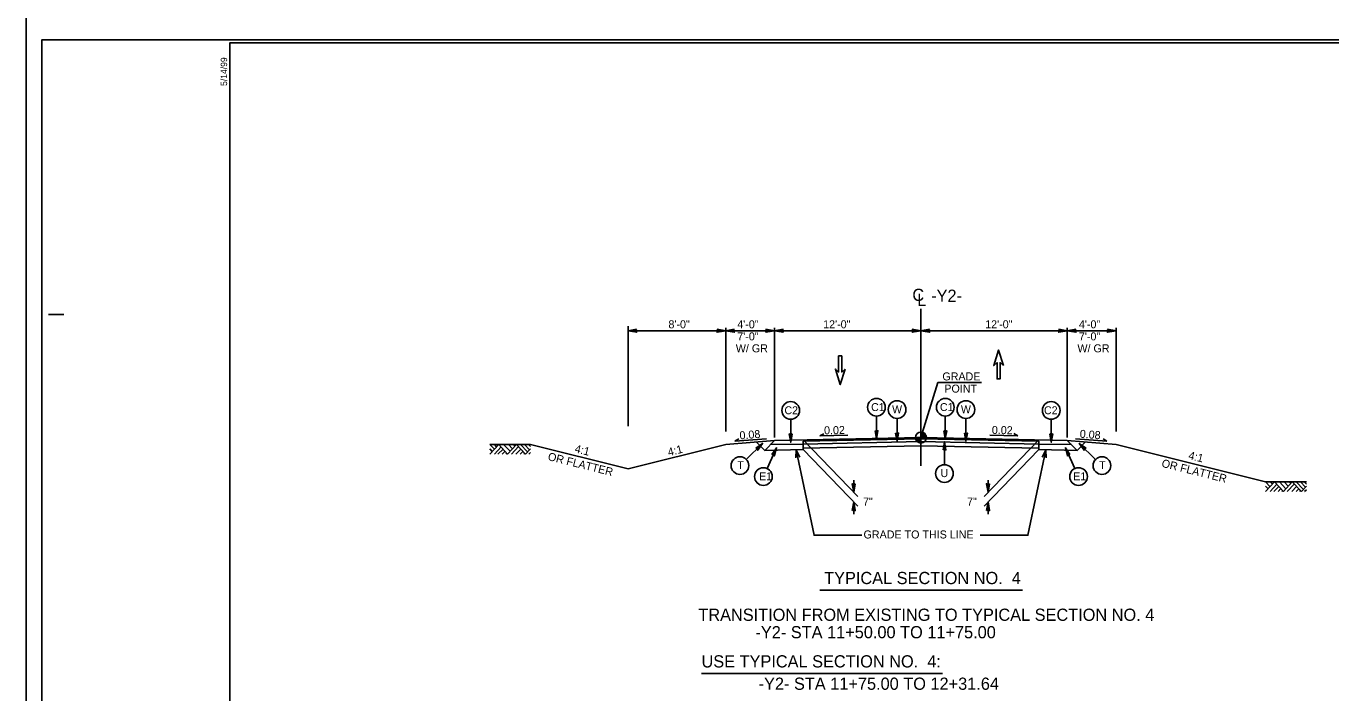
# Model space of a CAD drawing. Extents: x 1901718 to 1902220, y 193828 to 194187.
# Drawn here: x 1901965.8 to 1902072.8, y 193882.3 to 193936.9 of the extents above; entities that cross this region are included whole.
import ezdxf

# ---------------------------------------------------------------- set-up
doc = ezdxf.new("R2010")
doc.units = 0
for name, color, linetype in [('Old_Level_1', 7, 'Continuous'), ('Old_Level_11', 7, 'Continuous'), ('Old_Level_2', 7, 'Continuous'), ('Old_Level_20', 7, 'Continuous'), ('Old_Level_3', 7, 'Continuous'), ('Prop Dimension', 7, 'Continuous'), ('Sheet Border Standard 30in CELL', 7, 'Continuous'), ('Sheet Cutting Line CELL', 7, 'Continuous'), ('Sheet Plot Border Inside CELL', 7, 'Continuous'), ('Sheet Plot Border Outside CELL', 7, 'Continuous'), ('Typical Terminator CELL', 7, 'Continuous')]:
    doc.layers.add(name, color=color, linetype=linetype)

# ---------------------------------------------------------------- blocks, each defined once
blk = doc.blocks.new('TERMINATOR')
at = {"layer": 'Typical Terminator CELL'}
blk.add_lwpolyline([(-0.469, 0.081), (0, 0), (-0.471, -0.083), (-0.411, 0)], close=True, dxfattribs=at)

msp = doc.modelspace()

# ---------------------------------------------------------------- linework, layer by layer
at = {"layer": 'Old_Level_1'}
for p, q in [((1902039.18, 193900.87), (1902039.18, 193913.73)), ((1902023.18, 193903.68), (1902023.18, 193912.18)), ((1902027.18, 193903.18), (1902027.18, 193912.18)), ((1902051.18, 193903.18), (1902051.18, 193912.18)), ((1902055.18, 193903.68), (1902055.18, 193912.18)), ((1902015.18, 193911.93), (1902023.18, 193911.93)), ((1902023.18, 193911.93), (1902027.18, 193911.93)), ((1902027.18, 193911.93), (1902039.18, 193911.93)), ((1902051.18, 193911.93), (1902039.18, 193911.93)), ((1902055.18, 193911.93), (1902051.18, 193911.93)), ((1902039.18, 193903.18), (1902039.18, 193903.63)), ((1902047.12, 193903.32), (1902046.8, 193903.51)), ((1902003.84, 193902.62), (1902004.22, 193902.22)), ((1902003.84, 193901.81), (1902004.58, 193902.61)), ((1902004.22, 193902.62), (1902004.4, 193902.42)), ((1902004.58, 193902.61), (1902005.31, 193901.83)), ((1902004.97, 193902.62), (1902005.51, 193902.05)), ((1902005.31, 193901.83), (1902006.04, 193902.62)), ((1902005.37, 193902.62), (1902005.71, 193902.26)), ((1902005.62, 193901.81), (1902006.2, 193902.44)), ((1902005.77, 193902.62), (1902005.91, 193902.48)), ((1902006.04, 193902.62), (1902006.78, 193901.82)), ((1902006.36, 193902.62), (1902006.94, 193902)), ((1902006.69, 193902.62), (1902007.11, 193902.17)), ((1902007.01, 193902.62), (1902007.18, 193902.44)), ((1902007.18, 193902.62), (1902015.18, 193900.62)), ((1902023.18, 193902.62), (1902015.18, 193900.62)), ((1902027.18, 193902.94), (1902023.18, 193902.62)), ((1902026.52, 193903.08), (1902023.94, 193902.87)), ((1902023.94, 193902.87), (1902024.26, 193903.06)), ((1902026.38, 193902.13), (1902025.69, 193902.82)), ((1902027.18, 193902.94), (1902026.38, 193902.13)), ((1902029.53, 193902.65), (1902026.84, 193902.6)), ((1902039.18, 193903.18), (1902027.18, 193902.94)), ((1902039.18, 193903.07), (1902029.53, 193902.88)), ((1902029.53, 193902.99), (1902034, 193898.36)), ((1902029.53, 193902.88), (1902029.53, 193902.19)), ((1902039.18, 193902.85), (1902029.53, 193902.65)), ((1902039.18, 193902.51), (1902029.54, 193902.32)), ((1902030.9, 193903.32), (1902031.23, 193903.49)), ((1902033.2, 193903.37), (1902030.9, 193903.32)), ((1902038.73, 193903.18), (1902039.18, 193903.18)), ((1902039.63, 193903.18), (1902039.18, 193903.18)), ((1902039.18, 193902.73), (1902039.18, 193903.18)), ((1902039.18, 193903.18), (1902039.18, 193902.73)), ((1902039.18, 193903.18), (1902051.18, 193902.94)), ((1902039.18, 193903.07), (1902048.84, 193902.88)), ((1902039.18, 193902.85), (1902048.84, 193902.65)), ((1902039.18, 193902.51), (1902048.83, 193902.32)), ((1902048.84, 193902.99), (1902044.36, 193898.36)), ((1902044.82, 193903.37), (1902047.12, 193903.32)), ((1902048.84, 193902.88), (1902048.84, 193902.19)), ((1902048.84, 193902.65), (1902051.52, 193902.6)), ((1902051.18, 193902.94), (1902051.99, 193902.13)), ((1902051.18, 193902.94), (1902055.18, 193902.62)), ((1902051.85, 193903.08), (1902054.43, 193902.87)), ((1902051.99, 193902.13), (1902052.68, 193902.82)), ((1902054.43, 193902.87), (1902054.11, 193903.06)), ((1902055.18, 193902.62), (1902067.43, 193899.56)), ((1902003.84, 193902.26), (1902004.05, 193902.03)), ((1902004.22, 193901.81), (1902004.77, 193902.41)), ((1902004.52, 193901.81), (1902004.93, 193902.24)), ((1902004.87, 193901.81), (1902005.1, 193902.06)), ((1902005.18, 193901.81), (1902005.25, 193901.89)), ((1902005.99, 193901.81), (1902006.39, 193902.24)), ((1902006.35, 193901.81), (1902006.57, 193902.05)), ((1902006.65, 193901.81), (1902006.72, 193901.89)), ((1902006.78, 193901.82), (1902007.18, 193902.26)), ((1902007.05, 193901.81), (1902007.18, 193901.96)), ((1902029.53, 193902.19), (1902026.38, 193902.13)), ((1902029.53, 193902.19), (1902034, 193897.57)), ((1902048.84, 193902.19), (1902044.36, 193897.57)), ((1902048.84, 193902.19), (1902051.99, 193902.13)), ((1902033.68, 193899.69), (1902033.68, 193898.69)), ((1902044.68, 193899.69), (1902044.68, 193898.69)), ((1902033.68, 193897.9), (1902033.68, 193896.9)), ((1902044.68, 193897.9), (1902044.68, 193896.9))]:
    msp.add_line(p, q, dxfattribs=at)
for points in [[(1902039.19, 193903.63), (1902039.19, 193903.63), (1902039.19, 193903.18)], [(1902039.2, 193903.63), (1902039.2, 193903.18)], [(1902039.21, 193903.63), (1902039.21, 193903.18)], [(1902039.21, 193903.63), (1902039.21, 193903.18)], [(1902039.22, 193903.63), (1902039.22, 193903.18)], [(1902039.23, 193903.63), (1902039.23, 193903.18)], [(1902039.24, 193903.62), (1902039.24, 193903.18)], [(1902039.25, 193903.62), (1902039.25, 193903.18)], [(1902039.26, 193903.62), (1902039.26, 193903.18)], [(1902039.27, 193903.62), (1902039.27, 193903.18)], [(1902039.28, 193903.62), (1902039.28, 193903.18)], [(1902039.29, 193903.62), (1902039.29, 193903.18)], [(1902039.3, 193903.61), (1902039.3, 193903.18)], [(1902039.3, 193903.61), (1902039.3, 193903.18)], [(1902039.31, 193903.61), (1902039.31, 193903.18)], [(1902039.32, 193903.61), (1902039.32, 193903.18)], [(1902039.33, 193903.6), (1902039.33, 193903.18)], [(1902039.34, 193903.6), (1902039.34, 193903.18)], [(1902039.35, 193903.6), (1902039.35, 193903.18)], [(1902039.36, 193903.59), (1902039.36, 193903.18)], [(1902039.37, 193903.59), (1902039.37, 193903.18)], [(1902039.38, 193903.58), (1902039.38, 193903.18)], [(1902039.39, 193903.58), (1902039.39, 193903.18)], [(1902039.39, 193903.58), (1902039.39, 193903.18)], [(1902039.4, 193903.57), (1902039.4, 193903.18)], [(1902039.41, 193903.57), (1902039.41, 193903.18)], [(1902039.42, 193903.56), (1902039.42, 193903.18)], [(1902039.43, 193903.55), (1902039.43, 193903.18)], [(1902039.44, 193903.55), (1902039.44, 193903.18)], [(1902039.45, 193903.54), (1902039.45, 193903.18)], [(1902039.46, 193903.54), (1902039.46, 193903.18)], [(1902039.47, 193903.53), (1902039.47, 193903.18)], [(1902039.48, 193903.52), (1902039.48, 193903.18)], [(1902039.48, 193903.51), (1902039.48, 193903.18)], [(1902039.49, 193903.5), (1902039.49, 193903.18)], [(1902039.5, 193903.5), (1902039.5, 193903.18)], [(1902003.84, 193902.62), (1902007.18, 193902.62)], [(1902038.74, 193903.18), (1902038.74, 193903.13)], [(1902038.74, 193903.18), (1902038.74, 193903.08)], [(1902038.75, 193903.18), (1902038.75, 193903.04)], [(1902038.76, 193903.18), (1902038.76, 193903.02)], [(1902038.77, 193903.18), (1902038.77, 193903)], [(1902038.78, 193903.18), (1902038.78, 193902.98)], [(1902038.79, 193903.18), (1902038.79, 193902.96)], [(1902038.8, 193903.18), (1902038.8, 193902.94)], [(1902038.81, 193903.18), (1902038.81, 193902.93)], [(1902038.82, 193903.18), (1902038.82, 193902.92)], [(1902038.83, 193903.18), (1902038.83, 193902.91)], [(1902038.83, 193903.18), (1902038.83, 193902.89)], [(1902038.84, 193903.18), (1902038.84, 193902.88)], [(1902038.85, 193903.18), (1902038.85, 193902.87)], [(1902038.86, 193903.18), (1902038.86, 193902.86)], [(1902038.87, 193903.18), (1902038.87, 193902.85)], [(1902038.88, 193903.18), (1902038.88, 193902.85)], [(1902038.89, 193903.18), (1902038.89, 193902.84)], [(1902038.9, 193903.18), (1902038.9, 193902.83)], [(1902038.91, 193903.18), (1902038.91, 193902.82)], [(1902038.92, 193903.18), (1902038.92, 193902.82)], [(1902038.92, 193903.18), (1902038.92, 193902.81)], [(1902038.93, 193903.18), (1902038.93, 193902.8)], [(1902038.94, 193903.18), (1902038.94, 193902.8)], [(1902038.95, 193903.18), (1902038.95, 193902.79)], [(1902038.96, 193903.18), (1902038.96, 193902.79)], [(1902038.97, 193903.18), (1902038.97, 193902.78)], [(1902038.98, 193903.18), (1902038.98, 193902.78)], [(1902038.99, 193903.18), (1902038.99, 193902.77)], [(1902039, 193903.18), (1902039, 193902.77)], [(1902039.01, 193903.18), (1902039.01, 193902.77)], [(1902039.01, 193903.18), (1902039.01, 193902.76)], [(1902039.02, 193903.18), (1902039.02, 193902.76)], [(1902039.03, 193903.18), (1902039.03, 193902.75)], [(1902039.04, 193903.18), (1902039.04, 193902.75)], [(1902039.05, 193903.18), (1902039.05, 193902.75)], [(1902039.06, 193903.18), (1902039.06, 193902.75)], [(1902039.07, 193903.18), (1902039.07, 193902.74)], [(1902039.08, 193903.18), (1902039.08, 193902.74)], [(1902039.09, 193903.18), (1902039.09, 193902.74)], [(1902039.1, 193903.18), (1902039.1, 193902.74)], [(1902039.1, 193903.18), (1902039.1, 193902.74)], [(1902039.11, 193903.18), (1902039.11, 193902.73)], [(1902039.12, 193903.18), (1902039.12, 193902.73)], [(1902039.13, 193903.18), (1902039.13, 193902.73)], [(1902039.14, 193903.18), (1902039.14, 193902.73)], [(1902039.15, 193903.18), (1902039.15, 193902.73)], [(1902039.16, 193903.18), (1902039.16, 193902.73)], [(1902039.17, 193903.18), (1902039.17, 193902.73)], [(1902039.18, 193903.18), (1902039.18, 193902.73), (1902039.18, 193902.73)], [(1902039.51, 193903.49), (1902039.51, 193903.18)], [(1902039.52, 193903.48), (1902039.52, 193903.18)], [(1902039.53, 193903.47), (1902039.53, 193903.18)], [(1902039.54, 193903.45), (1902039.54, 193903.18)], [(1902039.55, 193903.44), (1902039.55, 193903.18)], [(1902039.56, 193903.43), (1902039.56, 193903.18)], [(1902039.57, 193903.42), (1902039.57, 193903.18)], [(1902039.57, 193903.4), (1902039.57, 193903.18)], [(1902039.58, 193903.38), (1902039.58, 193903.18)], [(1902039.59, 193903.37), (1902039.59, 193903.18)], [(1902039.6, 193903.34), (1902039.6, 193903.18)], [(1902039.61, 193903.32), (1902039.61, 193903.18)], [(1902039.62, 193903.29), (1902039.62, 193903.18)], [(1902039.63, 193903.24), (1902039.63, 193903.18)], [(1902029.25, 193901.57), (1902028.96, 193902.18), (1902028.93, 193901.51)], [(1902028.96, 193902.18), (1902030.42, 193895.18), (1902034.33, 193895.18)], [(1902049.41, 193902.18), (1902047.95, 193895.18), (1902044.04, 193895.18)], [(1902049.12, 193901.57), (1902049.41, 193902.18), (1902049.44, 193901.51)], [(1902067.43, 193899.56), (1902070.77, 193899.56)]]:
    msp.add_lwpolyline(points, dxfattribs=at)
msp.add_circle((1902039.18, 193903.18), 0.45, dxfattribs=at)
for start, end in [(359.9905, 89.9905), (179.9905, 269.9905)]:
    msp.add_arc((1902039.18, 193903.18), 0.45, start, end, dxfattribs=at)
at = {"layer": 'Old_Level_11'}
for p, q in [((1902028.51, 193904.68), (1902028.51, 193902.8)), ((1902035.54, 193904.93), (1902035.54, 193903.06)), ((1902037.23, 193904.75), (1902037.23, 193902.87)), ((1902041.18, 193904.93), (1902041.18, 193903.06)), ((1902042.87, 193904.75), (1902042.87, 193902.87)), ((1902049.86, 193904.68), (1902049.86, 193902.8)), ((1902024.87, 193901.38), (1902026.2, 193902.7)), ((1902041.11, 193900.96), (1902041.11, 193902.83)), ((1902053.5, 193901.38), (1902052.16, 193902.7)), ((1902026.57, 193900.64), (1902027.35, 193902.34)), ((1902051.8, 193900.64), (1902051.02, 193902.34)), ((1902067.43, 193899.56), (1902067.8, 193899.15)), ((1902067.43, 193898.75), (1902068.17, 193899.55)), ((1902067.8, 193899.56), (1902067.99, 193899.36)), ((1902067.8, 193898.75), (1902068.35, 193899.35)), ((1902068.17, 193899.55), (1902068.89, 193898.77)), ((1902068.56, 193899.56), (1902069.09, 193898.98)), ((1902068.89, 193898.77), (1902069.62, 193899.56)), ((1902068.96, 193899.56), (1902069.29, 193899.2)), ((1902069.2, 193898.75), (1902069.79, 193899.38)), ((1902069.36, 193899.56), (1902069.49, 193899.41)), ((1902069.62, 193899.56), (1902070.36, 193898.76)), ((1902069.95, 193899.56), (1902070.53, 193898.93)), ((1902070.28, 193899.56), (1902070.69, 193899.11)), ((1902070.6, 193899.56), (1902070.77, 193899.37)), ((1902067.43, 193899.2), (1902067.63, 193898.97)), ((1902068.11, 193898.75), (1902068.51, 193899.18)), ((1902068.46, 193898.75), (1902068.68, 193899)), ((1902068.77, 193898.75), (1902068.84, 193898.83)), ((1902069.57, 193898.75), (1902069.97, 193899.18)), ((1902069.94, 193898.75), (1902070.16, 193898.99)), ((1902070.23, 193898.75), (1902070.3, 193898.83)), ((1902070.36, 193898.76), (1902070.77, 193899.2)), ((1902070.63, 193898.75), (1902070.77, 193898.9)), ((1902030.89, 193890.68), (1902047.52, 193890.68)), ((1902021.2, 193883.84), (1902040.94, 193883.84))]:
    msp.add_line(p, q, dxfattribs=at)
for points in [[(1902035.43, 193903.73), (1902035.54, 193903.06), (1902035.66, 193903.73), (1902035.54, 193903.65)], [(1902037.11, 193903.54), (1902037.23, 193902.87), (1902037.35, 193903.55), (1902037.23, 193903.46)], [(1902041.07, 193903.73), (1902041.18, 193903.06), (1902041.3, 193903.73), (1902041.18, 193903.65)], [(1902042.75, 193903.54), (1902042.87, 193902.87), (1902042.99, 193903.55), (1902042.87, 193903.46)], [(1902025.64, 193902.31), (1902026.2, 193902.7), (1902025.81, 193902.14), (1902025.78, 193902.28)], [(1902028.63, 193903.47), (1902028.51, 193902.8), (1902028.39, 193903.48), (1902028.51, 193903.39)], [(1902041, 193902.16), (1902041.11, 193902.83), (1902041.23, 193902.16), (1902041.11, 193902.24)], [(1902049.74, 193903.47), (1902049.86, 193902.8), (1902049.98, 193903.48), (1902049.86, 193903.39)], [(1902052.72, 193902.31), (1902052.16, 193902.7), (1902052.56, 193902.14), (1902052.58, 193902.28)], [(1902026.97, 193901.78), (1902027.35, 193902.34), (1902027.18, 193901.68), (1902027.1, 193901.81)], [(1902051.4, 193901.78), (1902051.02, 193902.34), (1902051.19, 193901.68), (1902051.26, 193901.81)]]:
    msp.add_lwpolyline(points, close=True, dxfattribs=at)
for centre in [(1902028.51, 193905.4), (1902035.54, 193905.66), (1902037.23, 193905.47), (1902041.18, 193905.66), (1902042.87, 193905.47), (1902049.86, 193905.4), (1902024.35, 193900.88), (1902054.02, 193900.88), (1902026.27, 193899.98), (1902041.11, 193900.23), (1902052.1, 193899.98)]:
    msp.add_circle(centre, 0.725, dxfattribs=at)
at = {"layer": 'Old_Level_3'}
for q in [(1902039.18, 193903.18), (1902044.14, 193907.7)]:
    msp.add_line((1902040.57, 193907.7), q, dxfattribs=at)
at = {"layer": 'Prop Dimension'}
msp.add_line((1902015.18, 193904.1), (1902015.18, 193912.3), dxfattribs=at)
for points in [[(1902045.94, 193909.07), (1902045.67, 193909.32), (1902045.67, 193907.98), (1902045.42, 193907.98), (1902045.42, 193909.32), (1902045.15, 193909.07), (1902045.54, 193910.34)], [(1902045.94, 193909.07), (1902045.67, 193909.32), (1902045.67, 193907.98), (1902045.42, 193907.98), (1902045.42, 193909.32), (1902045.15, 193909.07), (1902045.54, 193910.34)], [(1902032.96, 193908.79), (1902032.69, 193908.54), (1902032.69, 193909.87), (1902032.44, 193909.87), (1902032.44, 193908.54), (1902032.17, 193908.79), (1902032.57, 193907.52)], [(1902032.96, 193908.79), (1902032.69, 193908.54), (1902032.69, 193909.87), (1902032.44, 193909.87), (1902032.44, 193908.54), (1902032.17, 193908.79), (1902032.57, 193907.52)]]:
    msp.add_lwpolyline(points, close=True, dxfattribs=at)
at = {"layer": 'Sheet Border Standard 30in CELL'}
for p, q in [((1901982.64, 193935.51), (1901982.64, 193935.51)), ((1901967.69, 193913.26), (1901968.94, 193913.26))]:
    msp.add_line(p, q, dxfattribs=at)
msp.add_lwpolyline([(1902132.54, 193935.51), (1901982.54, 193935.51), (1901982.54, 193830.51), (1902132.54, 193830.51)], close=True, dxfattribs=at)
at = {"layer": 'Sheet Cutting Line CELL'}
msp.add_line((1901965.84, 193938.01), (1901965.84, 193828.01), dxfattribs=at)
at = {"layer": 'Sheet Plot Border Inside CELL'}
msp.add_lwpolyline([(1902133.79, 193935.77), (1901967.14, 193935.77), (1901967.14, 193830.26), (1902133.79, 193830.26)], close=True, dxfattribs=at)
at = {"layer": 'Sheet Plot Border Outside CELL'}
msp.add_lwpolyline([(1902134.24, 193938.01), (1901965.84, 193938.01), (1901965.84, 193828.01), (1902134.24, 193828.01)], close=True, dxfattribs=at)

# ---------------------------------------------------------------- block references
at = {"layer": 'Old_Level_1', "xscale": 1.5, "yscale": 1.5}
for p, rotation in [((1902033.68, 193898.69), -90), ((1902044.68, 193898.69), -90), ((1902033.68, 193897.9), 90), ((1902044.68, 193897.9), 90)]:
    msp.add_blockref('TERMINATOR', p, dxfattribs=dict(at, rotation=rotation))
at = {"layer": 'Prop Dimension', "xscale": 1.5, "yscale": -1.5, "rotation": 180}
for p in [(1902015.18, 193911.93), (1902023.18, 193911.93), (1902027.18, 193911.93), (1902039.18, 193911.93), (1902051.18, 193911.93)]:
    msp.add_blockref('TERMINATOR', p, dxfattribs=at)
at = {"layer": 'Prop Dimension', "xscale": 1.5, "yscale": 1.5}
for p in [(1902023.18, 193911.93), (1902027.18, 193911.93), (1902039.18, 193911.93), (1902051.18, 193911.93), (1902055.18, 193911.93)]:
    msp.add_blockref('TERMINATOR', p, dxfattribs=at)

# ---------------------------------------------------------------- texts
at = {"layer": 'Old_Level_1'}
for s, p in [('8\'-0"', (1902018.49, 193912.13)), ('12\'-0"', (1902031.17, 193912.13)), ('12\'-0"', (1902044.45, 193912.13)), ('4\'-0"', (1902052.13, 193912.13)), ('7\'-0"', (1902052.13, 193911.14)), ('W/ GR', (1902052.01, 193910.16)), ('GRADE TO THIS LINE', (1902034.48, 193894.91))]:
    msp.add_text(s, height=0.656, dxfattribs=at).set_placement(p)
for s, rotation, p in [('4\'-0"', 360, (1902024.13, 193912.13)), ('7\'-0"', 360, (1902024.13, 193911.14)), ('W/ GR', 360, (1902024.01, 193910.16)), ('4:1', 345.9638, (1902010.76, 193901.98)), ('4:1', 14.0362, (1902018.52, 193901.65)), ('OR FLATTER', 345.9638, (1902008.56, 193901.34)), ('OR FLATTER', 345.9638, (1902058.86, 193900.79)), ('4:1', 345.9638, (1902061.06, 193901.43))]:
    msp.add_text(s, height=0.656, rotation=rotation, dxfattribs=at).set_placement(p)
at = {"layer": 'Old_Level_11'}
for s, height, p in [('GRADE', 0.656, (1902040.94, 193907.86)), ('POINT', 0.656, (1902041.1, 193906.86)), ('TYPICAL SECTION NO.  4', 1, (1902031.25, 193891.17)), ('TRANSITION FROM EXISTING TO TYPICAL SECTION NO. 4', 1, (1902020.94, 193888.16)), ('-Y2- STA 11+50.00 TO 11+75.00', 1, (1902025.62, 193886.73)), ('USE TYPICAL SECTION NO.  4:', 1, (1902021.2, 193884.34)), ('-Y2- STA 11+75.00 TO 12+31.64', 1, (1902025.88, 193882.51))]:
    msp.add_text(s, height=height, dxfattribs=at).set_placement(p)
at = {"layer": 'Old_Level_2'}
msp.add_text('C', height=1, dxfattribs=at).set_placement((1902038.48, 193914.37))
for s, height, rotation, p in [('-Y2-', 1, 359.9469, (1902040.02, 193914.3)), ('L', 1, 359.9469, (1902038.88, 193913.97)), ('0.08', 0.656, 4.5739, (1902024.34, 193903.02)), ('0.02', 0.656, 1.1916, (1902031.25, 193903.44)), ('0.02', 0.656, 358.8084, (1902044.99, 193903.48)), ('0.08', 0.656, 355.4261, (1902052.18, 193903.17))]:
    msp.add_text(s, height=height, rotation=rotation, dxfattribs=at).set_placement(p)
at = {"layer": 'Old_Level_20'}
for s, p in [('C2', (1902028, 193905.09)), ('C1', (1902035.1, 193905.35)), ('W', (1902036.82, 193905.17)), ('C1', (1902040.74, 193905.35)), ('W', (1902042.46, 193905.17)), ('C2', (1902049.27, 193905.09)), ('E1', (1902025.92, 193899.68)), ('U', (1902040.79, 193899.94)), ('E1', (1902051.67, 193899.68)), ('T', (1902053.79, 193900.59)), ('7"', (1902034.44, 193897.61)), ('7"', (1902042.97, 193897.61))]:
    msp.add_text(s, height=0.649, dxfattribs=at).set_placement(p)
msp.add_text('T', height=0.649, rotation=360, dxfattribs=at).set_placement((1902024.14, 193900.59))
at = {"layer": 'Sheet Border Standard 30in CELL'}
msp.add_text('5/14/99', height=0.525, rotation=90, dxfattribs=at).set_placement((1901982.32, 193931.99))

doc.saveas('drawing.dxf')
